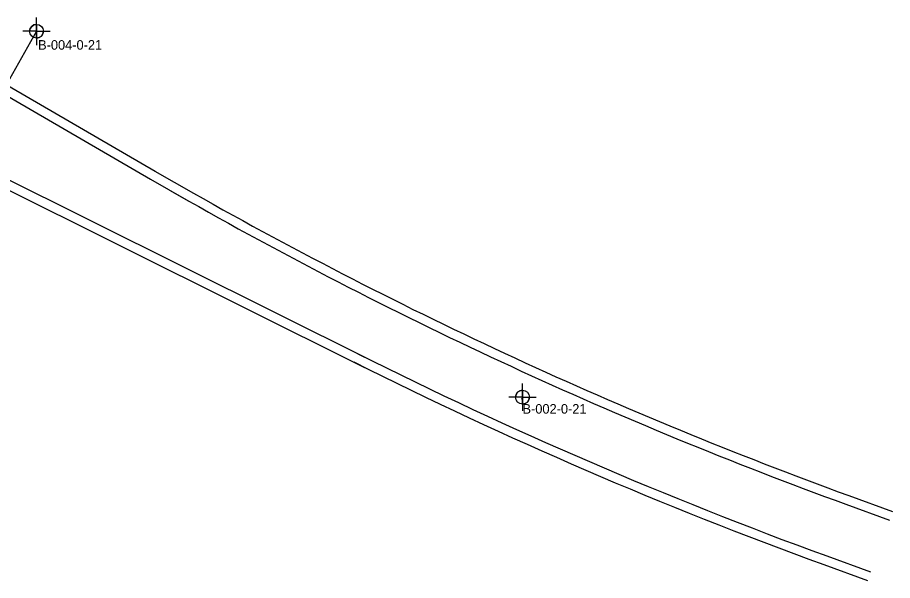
# Model space of a CAD drawing. Extents: x 2047259 to 2048296, y 456488 to 457733.
# Drawn here: x 2047915.1 to 2048296.2, y 456740 to 456985.1 of the extents above; entities that cross this region are included whole.
import ezdxf

# ---------------------------------------------------------------- set-up
doc = ezdxf.new("R2010")
doc.units = 0
for name, color, linetype in [('Default', 7, 'Continuous'), ('DT_X_Break_Line', 7, 'Continuous'), ('DT_X_Contour_Major', 7, 'Continuous'), ('DT_X_Contour_Minor', 7, 'Continuous')]:
    doc.layers.add(name, color=color, linetype=linetype)

msp = doc.modelspace()

# ---------------------------------------------------------------- linework, layer by layer
at = {"layer": 'Default'}
for p, q in [((2047923.42, 456979.1), (2047902.34, 456941.88)), ((2048135.08, 456819.79), (2048134.63, 456818.81))]:
    msp.add_line(p, q, dxfattribs=at)
at = {"layer": 'DT_X_Break_Line'}
for p, q in [((2047923.42, 456979.1), (2047923.42, 456985.1)), ((2047923.42, 456982.1), (2047923.42, 456979.1)), ((2047923.42, 456979.1), (2047917.42, 456979.1)), ((2047923.42, 456979.1), (2047920.42, 456979.1)), ((2047923.42, 456979.1), (2047923.42, 456973.1)), ((2047923.42, 456979.1), (2047929.42, 456979.1)), ((2047923.42, 456976.1), (2047923.42, 456979.1)), ((2047923.42, 456979.1), (2047926.42, 456979.1)), ((2048135.08, 456819.79), (2048135.08, 456825.79)), ((2048135.08, 456822.79), (2048135.08, 456819.79)), ((2048135.08, 456819.79), (2048129.08, 456819.79)), ((2048135.08, 456819.79), (2048132.08, 456819.79)), ((2048135.08, 456819.79), (2048135.08, 456813.79)), ((2048135.08, 456819.79), (2048141.08, 456819.79)), ((2048135.08, 456816.79), (2048135.08, 456819.79)), ((2048135.08, 456819.79), (2048138.08, 456819.79))]:
    msp.add_line(p, q, dxfattribs=at)
for centre in [(2047923.42, 456979.1), (2048135.08, 456819.79)]:
    msp.add_circle(centre, 3, dxfattribs=at)
for centre, start, end in [((2047923.42, 456979.1), 90, 180), ((2047923.42, 456979.1), 270, 360), ((2048135.08, 456819.79), 90, 180), ((2048135.08, 456819.79), 270, 360)]:
    msp.add_arc(centre, 3, start, end, dxfattribs=at)
at = {"layer": 'DT_X_Contour_Major'}
for p, q in [((2047897.7, 456958.44), (2047973.05, 456914.76)), ((2047903.47, 456918.35), (2048068.1, 456836.35)), ((2047973, 456914.67), (2047989.77, 456905.18)), ((2047981.35, 456909.94), (2047989.77, 456905.18)), ((2048275.88, 456773.21), (2048294.86, 456766.3)), ((2048275.88, 456773.21), (2048294.86, 456766.3)), ((2048267.67, 456750.66), (2048286.66, 456743.75))]:
    msp.add_line(p, q, dxfattribs=at)
for radius, start in [(1898, 240.47809), (1898, 240.47809), (1922, 243.36482)]:
    msp.add_arc((2048925.02, 458556.75), radius, start, 250.00047, dxfattribs=at)
at = {"layer": 'DT_X_Contour_Minor'}
for p, q in [((2047899.71, 456961.9), (2047975.06, 456918.22)), ((2047974.97, 456918.15), (2047991.74, 456908.66)), ((2047901.69, 456914.77), (2048066.32, 456832.77)), ((2048277.25, 456776.97), (2048296.23, 456770.06)), ((2048266.31, 456746.9), (2048285.29, 456739.99))]:
    msp.add_line(p, q, dxfattribs=at)
for radius, start in [(1894, 240.47809), (1926, 243.36482)]:
    msp.add_arc((2048925.02, 458556.75), radius, start, 250.00047, dxfattribs=at)

# ---------------------------------------------------------------- texts
at = {"layer": 'Default'}
for s, p in [('B-004-0-21', (2047924.1, 456971.08)), ('B-002-0-21', (2048135.08, 456812.63))]:
    msp.add_text(s, height=4.167, dxfattribs=at).set_placement(p)

doc.saveas('drawing.dxf')
